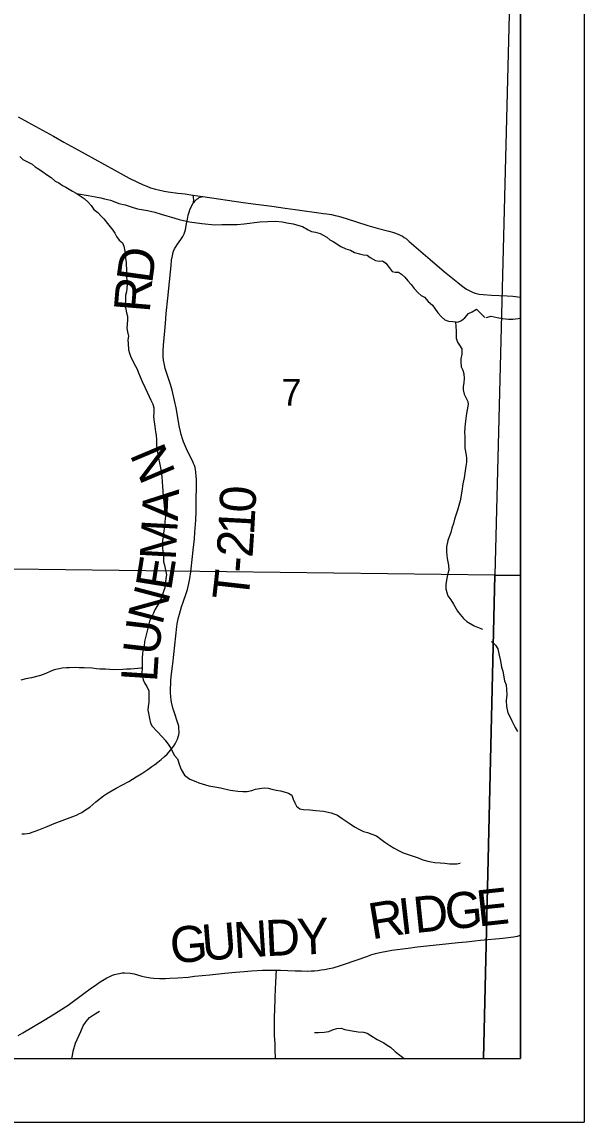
# Model space of a CAD drawing. Extents: x -19.9 to 41.9, y 0 to 32.3.
# Drawn here: x 8.114 to 9, y 14 to 15.733 of the extents above; entities that cross this region are included whole.
import ezdxf

# ---------------------------------------------------------------- set-up
doc = ezdxf.new("R2010")
doc.units = 0
for name, color, linetype in [('GM_X_Corporation', 7, 'Continuous'), ('GM_X_County_Road', 7, 'Continuous'), ('GM_X_County_Road_Text', 7, 'Continuous'), ('GM_X_Minor_River', 7, 'Continuous'), ('GM_X_Section_Text', 7, 'Continuous'), ('GM_X_Township_Road', 7, 'Continuous'), ('GM_X_Township_Road_Text', 7, 'Continuous'), ('SH_Data', 7, 'Continuous')]:
    doc.layers.add(name, color=color, linetype=linetype)

msp = doc.modelspace()

# ---------------------------------------------------------------- linework, layer by layer
at = {"layer": 'GM_X_Corporation'}
for points in [[(2.1, 17.918), (2.1, 14.1), (8.9, 14.1), (8.9, 17.8974), (7.9072, 17.9171), (7.5529, 17.9242), (7.3858, 17.9277), (6.9468, 17.937), (6.7, 17.9422), (6.3069, 17.9505), (6.2497, 17.9517), (6.2397, 17.9517), (5.9048, 17.9534), (5.761, 17.9543), (5.4954, 17.9559), (5.0257, 17.9637), (5.0192, 17.8403), (4.9169, 17.8392), (4.2613, 17.8672), (3.984, 17.879), (3.7505, 17.884), (2.973, 17.9007), (2.4715, 17.9106)], [(7.8246, 14.1), (8.9, 14.1), (8.9, 17.8974), (7.9072, 17.9171), (7.9012, 17.4524), (7.8776, 16.5173), (7.8702, 16.1679), (7.854, 15.4058), (7.8518, 15.3043)], [(8.8854, 15.8688), (8.8595, 14.8618), (7.8436, 14.8739), (7.8659, 15.8953)], [(8.9, 14.861), (8.9, 15.8686), (8.8854, 15.8688), (8.8595, 14.8618)], [(7.8255, 14.1), (8.8418, 14.1), (8.8595, 14.8618), (7.8436, 14.8739)], [(8.8418, 14.1), (8.9, 14.1), (8.9, 14.861), (8.8595, 14.8618)]]:
    msp.add_lwpolyline(points, close=True, dxfattribs=at)
at = {"layer": 'GM_X_County_Road'}
for points in [[(8.108, 15.5835), (8.1232, 15.5751), (8.1464, 15.5625), (8.1635, 15.553), (8.1801, 15.5437), (8.1972, 15.5344), (8.2135, 15.5256), (8.2591, 15.5002), (8.283, 15.4871), (8.2949, 15.4811), (8.3048, 15.4765), (8.3107, 15.4742), (8.3166, 15.472), (8.3243, 15.4698), (8.3292, 15.4685), (8.3381, 15.4667), (8.3443, 15.4654), (8.3598, 15.4635), (8.3713, 15.4621), (8.3832, 15.4605), (8.3993, 15.4582), (8.4627, 15.4489), (8.4827, 15.446), (8.5076, 15.4427), (8.529, 15.44), (8.5444, 15.4378), (8.5892, 15.4316), (8.5947, 15.4308), (8.6018, 15.4296), (8.6076, 15.4283), (8.6131, 15.4272), (8.6251, 15.4233), (8.6593, 15.4124), (8.6738, 15.408), (8.6921, 15.4036), (8.7003, 15.4013), (8.7036, 15.4001), (8.7068, 15.3989), (8.7104, 15.3974), (8.7136, 15.3957), (8.7166, 15.3935), (8.7199, 15.3912), (8.7246, 15.3875), (8.7574, 15.3587), (8.78, 15.3393), (8.801, 15.3224), (8.8067, 15.3179), (8.8112, 15.3147), (8.815, 15.3122), (8.818, 15.3104), (8.8219, 15.3083), (8.8251, 15.3069), (8.8286, 15.3056), (8.8319, 15.3047), (8.8349, 15.3041), (8.8408, 15.3036), (8.8542, 15.3029), (8.8788, 15.3017), (8.8876, 15.3009), (8.9, 15.2993)], [(8.1079, 14.1363), (8.1155, 14.1405), (8.1489, 14.1607), (8.1651, 14.1705), (8.1828, 14.1816), (8.1865, 14.1841), (8.2117, 14.2024), (8.2216, 14.2097), (8.2313, 14.2168), (8.2374, 14.2208), (8.2433, 14.2245), (8.2477, 14.227), (8.2523, 14.2293), (8.2566, 14.2311), (8.26, 14.2322), (8.2643, 14.2336), (8.2675, 14.2341), (8.2721, 14.2348), (8.2756, 14.235), (8.2844, 14.2344), (8.291, 14.2332), (8.3028, 14.2299), (8.3076, 14.2287), (8.3166, 14.2272), (8.322, 14.2267), (8.3307, 14.2263), (8.3401, 14.2263), (8.3468, 14.2264), (8.3597, 14.2269), (8.3759, 14.2284), (8.3861, 14.2295), (8.4101, 14.2319), (8.4336, 14.2343), (8.4506, 14.2359), (8.464, 14.2372), (8.4757, 14.2381), (8.4931, 14.239), (8.5008, 14.2393), (8.5152, 14.2394), (8.5216, 14.2393), (8.5445, 14.2383), (8.5545, 14.238), (8.5637, 14.2379), (8.5701, 14.2381), (8.5749, 14.2384), (8.5804, 14.2388), (8.5858, 14.2395), (8.5909, 14.2404), (8.5982, 14.2417), (8.6045, 14.2431), (8.6162, 14.2464), (8.6208, 14.248), (8.659, 14.2615), (8.6641, 14.2632), (8.6711, 14.2653), (8.678, 14.2669), (8.6919, 14.2697), (8.697, 14.2705), (8.7228, 14.2741), (8.7372, 14.2759), (8.7723, 14.2798), (8.8017, 14.2828), (8.814, 14.284), (8.8281, 14.2854), (8.8367, 14.2863), (8.8718, 14.2896), (8.8804, 14.2905), (8.889, 14.2918), (8.8952, 14.293), (8.8998, 14.2941), (8.9, 14.2942)]]:
    msp.add_lwpolyline(points, dxfattribs=at)
at = {"layer": 'GM_X_Minor_River'}
for points in [[(8.1103, 15.5214), (8.1153, 15.5162), (8.1229, 15.5129), (8.1298, 15.5092), (8.1348, 15.505), (8.1416, 15.5006), (8.1466, 15.4972), (8.1527, 15.4928), (8.16, 15.4879), (8.1665, 15.4823), (8.1719, 15.4797), (8.178, 15.4756), (8.1833, 15.4727), (8.1883, 15.4697), (8.1936, 15.4664), (8.1994, 15.4634), (8.207, 15.4582), (8.212, 15.4548), (8.2181, 15.4492), (8.2231, 15.444), (8.227, 15.4379), (8.2335, 15.4327), (8.2381, 15.4278), (8.2431, 15.423), (8.2489, 15.4154), (8.2531, 15.4106), (8.257, 15.4053), (8.2601, 15.4004), (8.2628, 15.3951), (8.2671, 15.3895), (8.2724, 15.385), (8.2744, 15.3801), (8.276, 15.3721), (8.2769, 15.3668), (8.2773, 15.3603), (8.2782, 15.3546), (8.2783, 15.3497), (8.2787, 15.3443), (8.2789, 15.3322), (8.2794, 15.3257), (8.2798, 15.32), (8.2795, 15.3132), (8.2785, 15.3078), (8.2774, 15.3021), (8.2771, 15.2964), (8.2765, 15.2857), (8.2777, 15.2804), (8.2786, 15.2751), (8.2802, 15.2698), (8.2803, 15.2641), (8.28, 15.2564), (8.2793, 15.2507), (8.2805, 15.245), (8.2818, 15.2382), (8.2807, 15.2325), (8.2812, 15.2264), (8.2821, 15.2165), (8.2837, 15.2112), (8.2857, 15.2052), (8.2931, 15.1908), (8.2954, 15.1859), (8.2978, 15.1802), (8.3001, 15.1738), (8.3033, 15.1666), (8.3076, 15.1575), (8.3111, 15.1496), (8.3142, 15.1428), (8.3173, 15.1371), (8.3201, 15.1307), (8.3217, 15.125), (8.3218, 15.1178), (8.3215, 15.1109), (8.3224, 15.103), (8.3236, 15.0957), (8.3245, 15.0874), (8.3253, 15.0821), (8.3258, 15.0745), (8.3259, 15.0668), (8.3264, 15.0611), (8.328, 15.052)], [(8.2001, 15.4629), (8.2183, 15.4595), (8.2301, 15.4574), (8.2381, 15.456), (8.2438, 15.4546), (8.2533, 15.4521), (8.2601, 15.4499), (8.2666, 15.4473), (8.2765, 15.4448), (8.2875, 15.4415), (8.2959, 15.4386), (8.3118, 15.4362), (8.3232, 15.4333), (8.3335, 15.4304), (8.3422, 15.4275), (8.3495, 15.4254), (8.3616, 15.4221), (8.3783, 15.4182), (8.3973, 15.4154), (8.4178, 15.4135), (8.4291, 15.414), (8.4416, 15.4138), (8.4534, 15.414), (8.464, 15.4153), (8.4889, 15.418), (8.501, 15.4189), (8.5135, 15.4191), (8.5245, 15.4181), (8.5313, 15.4167), (8.5416, 15.415), (8.5503, 15.4125), (8.556, 15.411), (8.5652, 15.4058), (8.5705, 15.4032), (8.5766, 15.4018), (8.5838, 15.3996), (8.5888, 15.3974), (8.5945, 15.3941), (8.5995, 15.39), (8.6045, 15.387), (8.6167, 15.3796), (8.6247, 15.3755), (8.6319, 15.3737), (8.638, 15.37), (8.646, 15.3679), (8.6525, 15.3661), (8.6582, 15.3658), (8.6631, 15.362), (8.6712, 15.3572), (8.6768, 15.3565), (8.6825, 15.3566), (8.6875, 15.3529), (8.6929, 15.3461), (8.6975, 15.3401), (8.7025, 15.3387), (8.7074, 15.3387), (8.7124, 15.3358), (8.7174, 15.3309), (8.722, 15.3253), (8.7277, 15.3196), (8.7324, 15.3132), (8.7385, 15.3061), (8.7435, 15.302), (8.7485, 15.2994), (8.7543, 15.2926), (8.7612, 15.2867), (8.765, 15.2818), (8.7697, 15.2746), (8.7754, 15.2686), (8.7804, 15.2637), (8.7861, 15.2619), (8.7933, 15.2613), (8.8013, 15.2603), (8.8069, 15.2626), (8.8122, 15.2669), (8.8178, 15.2738), (8.8238, 15.2766), (8.8305, 15.2805), (8.8439, 15.2673)], [(8.8459, 15.2673), (8.8534, 15.2696), (8.8632, 15.2673), (8.8716, 15.2657), (8.8807, 15.265), (8.8879, 15.2649), (8.8962, 15.266), (8.9, 15.2666)], [(8.7972, 15.261), (8.798, 15.2526), (8.7985, 15.2465), (8.7986, 15.2351), (8.8006, 15.2286), (8.8037, 15.2237), (8.8072, 15.2181), (8.8073, 15.2097), (8.8059, 15.2025), (8.806, 15.1975), (8.8065, 15.1899), (8.8092, 15.1843), (8.8104, 15.1786), (8.8109, 15.1713), (8.8106, 15.1649), (8.8096, 15.1584), (8.8093, 15.1534), (8.8109, 15.1466), (8.8136, 15.1417), (8.8171, 15.1353), (8.8172, 15.1303), (8.8155, 15.1193), (8.8141, 15.1124), (8.8127, 15.1002), (8.812, 15.0945), (8.8114, 15.0857), (8.8119, 15.0804), (8.8122, 15.0614), (8.8142, 15.0507), (8.8147, 15.0458), (8.8147, 15.0397), (8.8137, 15.0332), (8.8109, 15.0149), (8.8092, 15.0054), (8.8075, 14.9939), (8.8047, 14.9787), (8.8003, 14.9641), (8.796, 14.95), (8.7942, 14.9427), (8.7917, 14.9354), (8.7899, 14.9286), (8.7873, 14.9221), (8.7851, 14.9163), (8.7834, 14.906), (8.7831, 14.8984), (8.7844, 14.8878), (8.7864, 14.8775), (8.7869, 14.8695), (8.7851, 14.8642), (8.7841, 14.8592), (8.783, 14.8535), (8.7823, 14.847), (8.7821, 14.8398), (8.7837, 14.8341), (8.7853, 14.8292), (8.7899, 14.8228), (8.7942, 14.816), (8.8008, 14.8047), (8.8046, 14.7998), (8.81, 14.7934), (8.8154, 14.7885), (8.8268, 14.7818), (8.8345, 14.7785), (8.8402, 14.7767)], [(8.328, 15.052), (8.3293, 15.046), (8.3305, 15.0384), (8.3329, 15.0281), (8.3346, 15.0171), (8.3351, 15.0088), (8.3356, 15.0012), (8.3361, 14.9943), (8.3366, 14.9856), (8.3374, 14.9772), (8.3379, 14.9715), (8.3388, 14.9654), (8.34, 14.9601), (8.3401, 14.9544), (8.3394, 14.946), (8.3384, 14.9384), (8.337, 14.9277), (8.3364, 14.9212), (8.3357, 14.9163), (8.3355, 14.9037), (8.3364, 14.895), (8.3368, 14.8897), (8.3373, 14.8824), (8.3385, 14.8771), (8.3397, 14.8722), (8.3406, 14.8673), (8.3418, 14.8623), (8.3407, 14.8562), (8.3401, 14.8505), (8.339, 14.8417), (8.3372, 14.8356), (8.334, 14.8264), (8.3299, 14.8176), (8.3233, 14.8069), (8.3211, 14.8019), (8.3148, 14.7892), (8.3127, 14.7801), (8.3113, 14.7736), (8.3073, 14.7568), (8.3067, 14.7495), (8.3038, 14.7392), (8.3036, 14.7304), (8.3034, 14.7152), (8.3031, 14.7076), (8.304, 14.7027), (8.3052, 14.6966), (8.3076, 14.6909), (8.3107, 14.686), (8.3138, 14.6792), (8.314, 14.6617), (8.313, 14.6548), (8.3123, 14.6491), (8.3132, 14.6442), (8.3152, 14.6355), (8.3168, 14.6286), (8.3191, 14.6237), (8.3272, 14.6155), (8.3353, 14.6065), (8.3399, 14.6016), (8.3453, 14.5937), (8.3484, 14.5888), (8.3539, 14.5782), (8.3593, 14.5722), (8.3624, 14.562), (8.3648, 14.5555), (8.3702, 14.5465), (8.3787, 14.5401), (8.3878, 14.5365), (8.3928, 14.5343), (8.4083, 14.5296), (8.4178, 14.5278), (8.4269, 14.5264), (8.4334, 14.525), (8.4425, 14.5229), (8.4543, 14.5211), (8.4622, 14.5205), (8.4687, 14.5206), (8.4762, 14.5222), (8.4823, 14.5242), (8.4883, 14.5255), (8.4955, 14.5263), (8.5019, 14.526), (8.508, 14.5246), (8.5145, 14.5228), (8.5213, 14.5218), (8.5274, 14.52), (8.5342, 14.5182), (8.5392, 14.5148), (8.5416, 14.5084), (8.5443, 14.5031), (8.5466, 14.4978), (8.552, 14.4933), (8.5577, 14.4923), (8.5679, 14.4917), (8.5774, 14.491), (8.5895, 14.4897), (8.6013, 14.4872), (8.6112, 14.4832), (8.6189, 14.4784), (8.625, 14.4739), (8.6311, 14.4698)], [(8.8542, 14.757), (8.8603, 14.7513), (8.864, 14.7455), (8.8663, 14.7353), (8.8681, 14.7265), (8.87, 14.7166), (8.8718, 14.7102), (8.8744, 14.695), (8.8771, 14.6885), (8.8778, 14.6813), (8.8781, 14.6729), (8.8773, 14.6642), (8.8777, 14.6547), (8.8799, 14.6444), (8.8837, 14.6376), (8.8863, 14.6318), (8.8912, 14.6216), (8.8953, 14.6151)], [(8.3033, 14.7152), (8.3019, 14.7148), (8.2966, 14.7143), (8.2906, 14.7139), (8.2849, 14.7134), (8.2788, 14.7133), (8.2732, 14.7128), (8.258, 14.7126), (8.2455, 14.7132), (8.2368, 14.7134), (8.2315, 14.7141), (8.2247, 14.7148), (8.2118, 14.7153), (8.2042, 14.7156), (8.1981, 14.7159), (8.1891, 14.7157), (8.1841, 14.7153), (8.1773, 14.7152), (8.1724, 14.714), (8.1649, 14.7123), (8.1585, 14.7096), (8.1517, 14.7064), (8.143, 14.7036), (8.1287, 14.7), (8.12, 14.6983), (8.1121, 14.6963)], [(8.6311, 14.4698), (8.6384, 14.465), (8.6452, 14.4613), (8.6525, 14.4576), (8.6589, 14.4561), (8.6654, 14.4536), (8.6726, 14.4506), (8.6799, 14.4458), (8.686, 14.441), (8.6937, 14.4354), (8.7006, 14.4313), (8.7097, 14.4265), (8.7147, 14.4243), (8.7227, 14.4217), (8.7276, 14.4199), (8.7386, 14.4163), (8.7459, 14.4133), (8.7539, 14.4108), (8.7588, 14.4097), (8.7649, 14.4087), (8.7732, 14.4084), (8.7804, 14.4078), (8.788, 14.4067), (8.7997, 14.4069), (8.8046, 14.4078), (8.8041, 14.4081)], [(8.1925, 14.1), (8.1934, 14.1049), (8.1945, 14.1118), (8.1984, 14.1244), (8.201, 14.1302), (8.2043, 14.1367), (8.2069, 14.1428), (8.2105, 14.1516), (8.215, 14.1586), (8.2206, 14.1644), (8.2266, 14.1686), (8.236, 14.1745)], [(8.5753, 14.1412), (8.5814, 14.141), (8.5905, 14.1415), (8.5976, 14.1427), (8.6036, 14.1451), (8.6101, 14.1471), (8.6169, 14.1476), (8.6229, 14.1458), (8.6313, 14.1444), (8.6442, 14.1419), (8.6522, 14.1413), (8.6582, 14.1399), (8.664, 14.1365), (8.6739, 14.1298), (8.6842, 14.1246), (8.6896, 14.1209), (8.6949, 14.118), (8.7022, 14.1112), (8.7076, 14.1071), (8.7137, 14.1023), (8.7163, 14.1)]]:
    msp.add_lwpolyline(points, dxfattribs=at)
at = {"layer": 'GM_X_Township_Road'}
for points in [[(8.3839, 15.4481), (8.3842, 15.4488), (8.3845, 15.4501), (8.3848, 15.4517), (8.3845, 15.457), (8.3841, 15.4583), (8.3837, 15.4595), (8.3832, 15.4605)], [(8.3513, 14.7186), (8.3517, 14.7216), (8.3581, 14.7806), (8.3587, 14.7847), (8.3596, 14.7902), (8.3608, 14.7948), (8.3621, 14.8003), (8.3656, 14.8118), (8.3683, 14.8191), (8.3734, 14.834), (8.3749, 14.8389), (8.377, 14.8484), (8.3786, 14.8564), (8.3799, 14.8668), (8.383, 14.8909), (8.384, 14.901), (8.3859, 14.9189), (8.3867, 14.9294), (8.3879, 14.9481), (8.3886, 14.9623), (8.3887, 14.9675), (8.3889, 15.0133), (8.3888, 15.0169), (8.3881, 15.0245), (8.3876, 15.0275), (8.3868, 15.0311), (8.3858, 15.0345), (8.3846, 15.0376), (8.3833, 15.0407), (8.3783, 15.0505), (8.3731, 15.0608), (8.3715, 15.0642), (8.3686, 15.0715), (8.3674, 15.075), (8.3648, 15.0832), (8.3637, 15.0877), (8.3619, 15.0966), (8.3606, 15.1036), (8.357, 15.1252), (8.3542, 15.1369), (8.3507, 15.153), (8.3482, 15.1617), (8.3398, 15.187), (8.3385, 15.1929), (8.3372, 15.2002), (8.3367, 15.2058), (8.3363, 15.2099), (8.3365, 15.2138), (8.3371, 15.2238), (8.34, 15.258), (8.3414, 15.2737), (8.3441, 15.2981), (8.3489, 15.3496), (8.3499, 15.3576), (8.3511, 15.3644), (8.3519, 15.3685), (8.353, 15.372), (8.3546, 15.3755), (8.3565, 15.3789), (8.3589, 15.383), (8.3643, 15.3905), (8.3673, 15.3949), (8.3686, 15.3972), (8.3697, 15.3993), (8.3709, 15.4025), (8.3716, 15.4054), (8.373, 15.4126), (8.3747, 15.4223), (8.3761, 15.4286), (8.3774, 15.4336), (8.3787, 15.4372), (8.3839, 15.4481), (8.3852, 15.4494), (8.3866, 15.4509), (8.3882, 15.4526), (8.3896, 15.4538), (8.3915, 15.4552), (8.3935, 15.4563), (8.3951, 15.457), (8.3972, 15.4577), (8.3993, 15.4582)], [(8.1138, 14.4541), (8.1179, 14.4539), (8.1222, 14.4543), (8.1262, 14.4551), (8.1302, 14.4564), (8.1349, 14.4581), (8.1403, 14.4602), (8.1535, 14.4657), (8.1647, 14.4702), (8.1815, 14.4768), (8.194, 14.4813), (8.1999, 14.4836), (8.2037, 14.4853), (8.2082, 14.4878), (8.2127, 14.4907), (8.2208, 14.4962), (8.2255, 14.5), (8.2306, 14.5042), (8.2426, 14.5138), (8.247, 14.5169), (8.2522, 14.5204), (8.2624, 14.5261), (8.2822, 14.5366), (8.2941, 14.5436), (8.3031, 14.5493), (8.3123, 14.5556), (8.3187, 14.56), (8.3233, 14.5632), (8.3281, 14.5669), (8.3334, 14.5711), (8.3385, 14.5757), (8.3427, 14.5796), (8.3461, 14.5831), (8.3501, 14.5883), (8.3529, 14.5918), (8.3553, 14.5958), (8.3575, 14.5999), (8.359, 14.6033), (8.3601, 14.6067), (8.361, 14.6101), (8.3615, 14.6134), (8.3613, 14.621), (8.361, 14.6237), (8.3602, 14.6267), (8.3531, 14.6476), (8.3524, 14.6502), (8.3499, 14.6614), (8.3493, 14.6651), (8.3487, 14.6694), (8.3482, 14.6766), (8.3481, 14.6834), (8.3484, 14.6904), (8.3486, 14.6955), (8.3492, 14.7016), (8.3513, 14.7186)], [(8.5134, 14.1), (8.5131, 14.114), (8.5129, 14.1238), (8.5123, 14.136), (8.512, 14.1547), (8.5121, 14.1615), (8.5126, 14.1809), (8.5129, 14.1896), (8.5132, 14.1993), (8.5135, 14.2065), (8.5137, 14.2113), (8.5139, 14.2176), (8.5142, 14.2218), (8.5145, 14.2276), (8.5148, 14.2328), (8.5151, 14.2375), (8.5152, 14.2394)]]:
    msp.add_lwpolyline(points, dxfattribs=at)
at = {"layer": 'SH_Data'}
for p, q in [((9, 21), (9, 14)), ((8.9, 20.9), (8.9, 14.1)), ((2.1, 14.1), (8.9, 14.1)), ((2, 14), (9, 14))]:
    msp.add_line(p, q, dxfattribs=at)

# ---------------------------------------------------------------- texts
at = {"layer": 'GM_X_County_Road_Text'}
for s, rotation, p in [('E', 6.1537, (8.8337, 14.3079)), ('R', 9.3186, (8.6656, 14.2875)), ('I', 6.485, (8.7109, 14.295)), ('D', 5.9226, (8.7339, 14.2976)), ('G', 5.8933, (8.7836, 14.3027)), ('N', 3.7402, (8.4491, 14.2579)), ('D', 2.5763, (8.4987, 14.2612)), ('Y', 2.3758, (8.5486, 14.2634)), ('G', 4.763, (8.3497, 14.2497)), ('U', 4.6826, (8.3995, 14.2539))]:
    msp.add_text(s, height=0.0568, rotation=rotation, dxfattribs=at).set_placement(p)
at = {"layer": 'GM_X_Section_Text'}
msp.add_text('7', height=0.0419, rotation=0, dxfattribs=at).set_placement((8.5233, 15.1288))
at = {"layer": 'GM_X_Township_Road_Text'}
for s, rotation, p in [('D', 82.1543, (8.319, 15.3199)), ('R', 85.2642, (8.3152, 15.2742)), ('N', 112.8266, (8.357, 15.0232)), ('A', 87.4723, (8.3596, 14.9464)), ('0', 87.0769, (8.4816, 14.959)), ('1', 86.9061, (8.4797, 14.9238)), ('M', 86.9713, (8.3563, 14.8843)), ('2', 86.1942, (8.4773, 14.8882)), ('E', 80.8826, (8.3489, 14.8358)), ('-', 85.4214, (8.4754, 14.8641)), ('T', 83.558, (8.4704, 14.8198)), ('N', 75.2711, (8.3349, 14.7815)), ('U', 83.227, (8.3294, 14.7339)), ('L', 86.2817, (8.3267, 14.6923))]:
    msp.add_text(s, height=0.0568, rotation=rotation, dxfattribs=at).set_placement(p)

doc.saveas('drawing.dxf')
